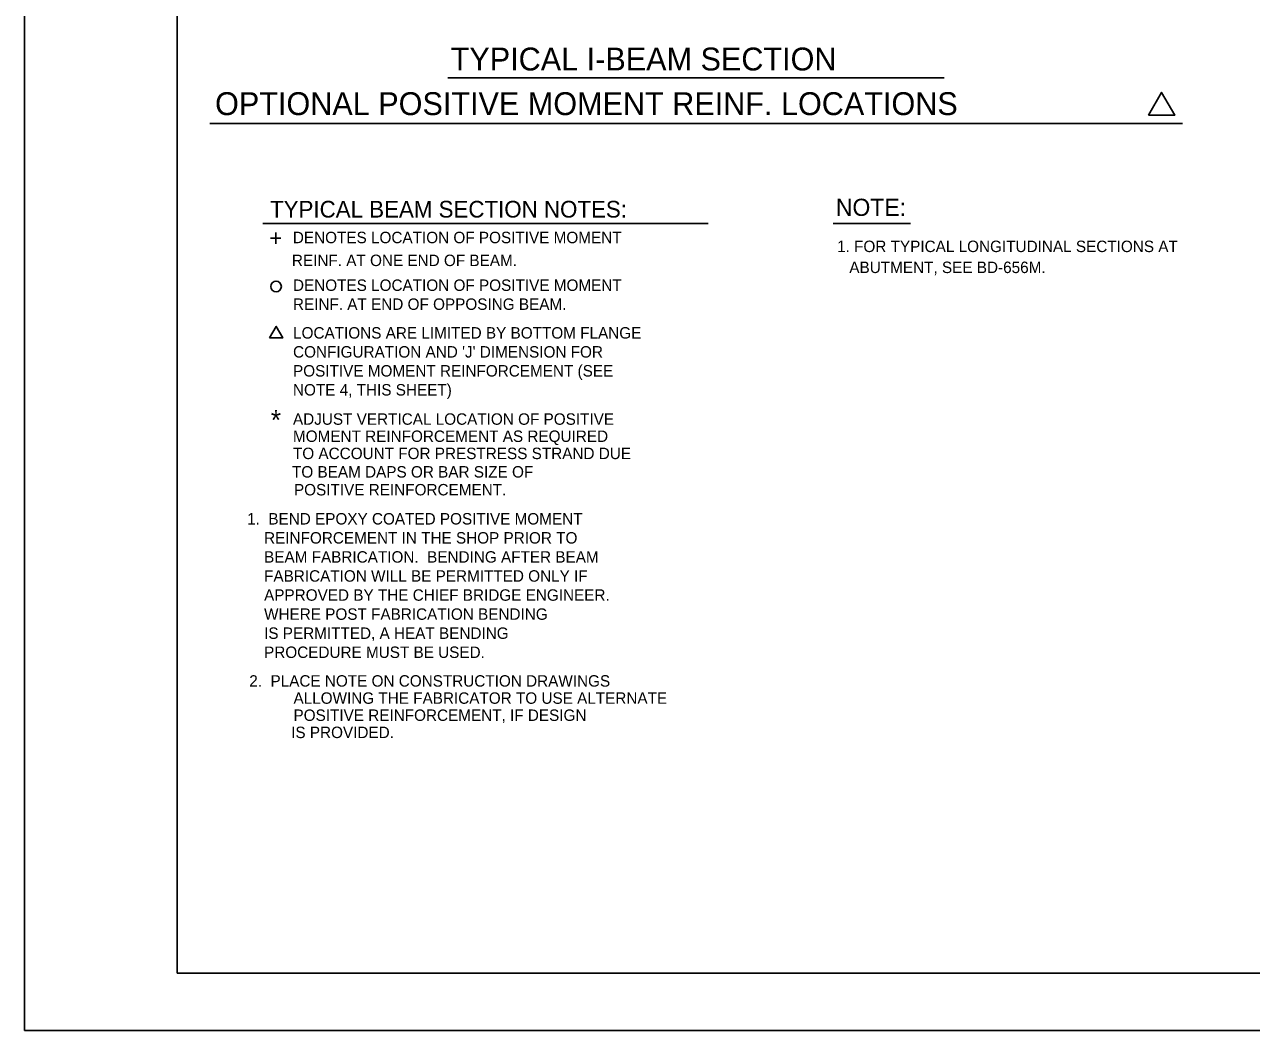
# Model space of a CAD drawing. Extents: x 639980 to 641204, y 298038 to 300414.
# Drawn here: x 639980.3 to 640302.1, y 298037.8 to 298301.5 of the extents above; entities that cross this region are included whole.
import ezdxf

# ---------------------------------------------------------------- set-up
doc = ezdxf.new("R2010")
doc.units = 0
for name, color, linetype in [('1', 7, 'Continuous'), ('2', 7, 'Continuous'), ('3', 7, 'Continuous'), ('PLT-BNDY', 7, 'Continuous')]:
    doc.layers.add(name, color=color, linetype=linetype)

msp = doc.modelspace()

# ---------------------------------------------------------------- linework, layer by layer
at = {"layer": '2'}
for p, q in [((640020.31, 298052.78), (640020.31, 298616.78)), ((640091.37, 298287.53), (640221.55, 298287.53)), ((640278.57, 298283.75), (640275.11, 298277.75)), ((640278.57, 298283.75), (640282.04, 298277.75)), ((640028.88, 298275.6), (640284.05, 298275.6)), ((640275.11, 298277.75), (640282.04, 298277.75)), ((640192.46, 298249.33), (640212.72, 298249.33)), ((640046.19, 298246.98), (640046.19, 298244.06)), ((640047.55, 298245.48), (640044.79, 298245.48)), ((640046.33, 298222.36), (640044.59, 298219.36)), ((640046.33, 298222.36), (640048.06, 298219.36)), ((640044.59, 298219.36), (640048.06, 298219.36)), ((640806.31, 298052.78), (640020.31, 298052.78))]:
    msp.add_line(p, q, dxfattribs=at)
for points in [[(640275.11, 298277.75), (640278.57, 298283.75), (640282.04, 298277.75)], [(640044.59, 298219.36), (640046.33, 298222.36), (640048.06, 298219.36)]]:
    msp.add_lwpolyline(points, close=True, dxfattribs=at)
msp.add_circle((640046.29, 298232.86), 1.4, dxfattribs=at)
at = {"layer": '3'}
msp.add_line((640042.85, 298249.33), (640159.64, 298249.33), dxfattribs=at)
at = {"layer": 'PLT-BNDY'}
msp.add_lwpolyline([(639980.31, 298631.78), (640821.31, 298631.78), (640821.31, 298037.78), (639980.31, 298037.78)], close=True, dxfattribs=at)

# ---------------------------------------------------------------- texts
at = {"layer": '1'}
msp.add_text('TYPICAL BEAM SECTION NOTES:', height=4.375, dxfattribs=at).set_placement((640044.71, 298250.93))
at = {"layer": '2'}
for s, height, p in [('TYPICAL I-BEAM SECTION', 6.0002, (640092.09, 298289.49)), ('OPTIONAL POSITIVE MOMENT REINF. LOCATIONS', 6, (640030.29, 298277.79)), ('NOTE:', 4.5, (640193.14, 298251.36)), ('1. FOR TYPICAL LONGITUDINAL SECTIONS AT', 3, (640193.45, 298241.87)), ('   ABUTMENT, SEE BD-656M.', 3, (640193.32, 298236.37))]:
    msp.add_text(s, height=height, dxfattribs=at).set_placement(p)
at = {"layer": '3'}
for s, height, p in [('DENOTES LOCATION OF POSITIVE MOMENT', 2.999, (640050.69, 298244.2)), ('REINF. AT ONE END OF BEAM.', 2.999, (640050.44, 298238.2)), ('DENOTES LOCATION OF POSITIVE MOMENT', 2.999, (640050.72, 298231.69)), ('REINF. AT END OF OPPOSING BEAM.', 2.999, (640050.71, 298226.72)), ('LOCATIONS ARE LIMITED BY BOTTOM FLANGE', 2.999, (640050.75, 298219.19)), ("CONFIGURATION AND 'J' DIMENSION FOR", 2.999, (640050.74, 298214.21)), ('POSITIVE MOMENT REINFORCEMENT (SEE ', 2.999, (640050.73, 298209.24)), ('NOTE 4, THIS SHEET)', 2.999, (640050.72, 298204.26)), ('*', 5.18, (640044.91, 298195.25)), ('ADJUST VERTICAL LOCATION OF POSITIVE', 2.999, (640050.72, 298196.59)), ('MOMENT REINFORCEMENT AS REQUIRED', 2.999, (640050.72, 298192.09)), ('TO ACCOUNT FOR PRESTRESS STRAND DUE', 2.999, (640050.72, 298187.59)), ('TO BEAM DAPS OR BAR SIZE OF', 2.999, (640050.47, 298182.75)), ('POSITIVE REINFORCEMENT.', 2.999, (640050.98, 298178.07)), ('1.  BEND EPOXY COATED POSITIVE MOMENT', 2.9979, (640038.69, 298170.44)), ('    REINFORCEMENT IN THE SHOP PRIOR TO ', 2.9979, (640038.69, 298165.44)), ('    BEAM FABRICATION.  BENDING AFTER BEAM', 2.9979, (640038.69, 298160.44)), ('    FABRICATION WILL BE PERMITTED ONLY IF', 2.9979, (640038.69, 298155.45)), ('    APPROVED BY THE CHIEF BRIDGE ENGINEER.', 2.9979, (640038.69, 298150.45)), ('    WHERE POST FABRICATION BENDING', 2.9979, (640038.69, 298145.45)), ('    IS PERMITTED, A HEAT BENDING', 2.9979, (640038.69, 298140.45)), ('    PROCEDURE MUST BE USED.', 2.9979, (640038.69, 298135.45)), ('2.  PLACE NOTE ON CONSTRUCTION DRAWINGS', 2.9979, (640039.26, 298127.93)), ('ALLOWING THE FABRICATOR TO USE ALTERNATE', 2.9979, (640050.86, 298123.43)), ('POSITIVE REINFORCEMENT, IF DESIGN', 2.9979, (640050.86, 298118.94)), ('IS PROVIDED.', 2.9979, (640050.25, 298114.44))]:
    msp.add_text(s, height=height, dxfattribs=at).set_placement(p)

doc.saveas('drawing.dxf')
